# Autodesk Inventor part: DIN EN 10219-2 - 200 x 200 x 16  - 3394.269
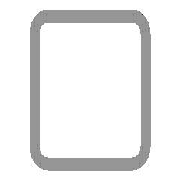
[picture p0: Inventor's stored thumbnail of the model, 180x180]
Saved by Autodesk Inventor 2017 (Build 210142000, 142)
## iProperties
IsCustomPart: 1
Created: 2016-02
Part Number: DIN EN 10219-2 - 200 x 200 x 16  - 3394.269
Material: Steel, Mild
Description: Cold formed welded structural hollow sections of non-alloy and fine grain structural steel
Document SubType Name: Modeling
Standard: DIN
Designer: iusti
Standard Revision: 2006-07
Standards Organization: DIN
Language: en-US
Size Designation: 200 x 200 x 16
Categories: <MemberInstance><Categories><Category DisplayName="Structural Shapes" InternalName="089c4875-fa83-4c05-b084-43b9cc11f5ed" Mnemonic="GRDR"><CategoryParameter Dis
Stock Number: 200 x 200 x 16
Density: 7.85 g/cm^3
Appearance: Semi-Polished
Mass: 259456 g
Surface Area: 41726.7 cm^2
Volume: 33051.7 cm^3
_CCFamilyMember: 103
_CCFamilyDisplayName: DIN EN 10219-2 (Square Hollow Section - Cold Formed) - Cold formed welded structural hollow sections of non-alloy and fine grain structural steel
_FrameMemberDoc: Frame Member File
_Version: 15.0.0
_GetPNFromCC: 1
G_L: 3394.269 mm
G_W: 200.000 mm
G_H: 200.000 mm
+04F2D6EA-35C4-4CFB-B988-CDC8EB8D103C+CUTDETAIL1: Cut
+DAF749EB-893C-4754-AD4A-1A621FA4CB9E+CUTDETAIL2: Cut
Author: iusti
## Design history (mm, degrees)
node "Start plane"
node "End plane"
sketch "Sketch"
  geometry: L1 (-100, -52)-(-100, 52); L2 (-52, 100)-(52, 100); L3 (100, 52)-(100, -52); L4 (52, -100)-(-52, -100); L5 (-52, 84)-(52, 84); L6 (84, 52)-(84, -52); L7 (52, -84)-(-52, -84); L8 (-84, -52)-(-84, 52); L9 (0, 153.918)-(0, -153.918) reference; L10 (-153.918, 0)-(153.918, 0) reference; A1 r 48 centre (-52, -52) between (-100, -52) and (-52, -100); A2 r 48 centre (-52, 52) between (-52, 100) and (-100, 52); A3 r 48 centre (52, 52) between (100, 52) and (52, 100); A4 r 48 centre (52, -52) between (52, -100) and (100, -52); A5 r 32 centre (-52, 52) between (-52, 84) and (-84, 52); A6 r 32 centre (52, 52) between (84, 52) and (52, 84); A7 r 32 centre (52, -52) between (52, -84) and (84, -52); A8 r 32 centre (-52, -52) between (-84, -52) and (-52, -84)
  constraints: 16 end point, 16 point on circle, 8 centre point, 8 tangent, 4 parallel, 3 equal radius, 2 perpendicular, 7 other
  dimensions: "d7" = 48 radius of A1 (= G_IR); "d10" = 200 distance between parallel lines of L2 L4 (= G_H); "d11" = 200 distance between parallel lines of L1 L3 (= G_W); "d12" = 16 distance between parallel lines of L3 L6 (= G_T); "d15" = 100 distance between parallel lines of L2 L10 (= 0.5 x d10); "d16" = 100 distance between parallel lines of L9 L3 (= 0.5 x d11)
extrude "Body" new body sketch "Sketch" stored distance "d3" = 3394.26947 (= G_L); taper "d4" = 0 deg
node "Driven Length"
  sketch "Sketch3"
    geometry: L1 (0, 0)-(10, 0) reference
    constraints: 2 end point, 1 horizontal
  workplane "Work Plane3"
  sketch "Sketch4"
    geometry: L1 (-2, 73.146)-(12, 73.146) reference; L2 (-2, 3467.416)-(12, 3467.416) reference
    dimensions: "d18" = 3394.26947 distance between parallel lines of L1 L2 (derived)
workplane "Work Plane4"
split "Split1"
workplane "Work Plane5"
split "Split2"
body "Solid1"
other parameters: "G_W" = 200 [user parameter; used in 1 equation term], "G_H" = 200 [user parameter; used in 1 equation term], "G_T" = 16 [user parameter; used in 1 equation term], "G_IR" = 48 [user parameter; used in 1 equation term], "G_L" = 3394.26947 (= d18) [user parameter; used in 1 equation term], "G_OFFSET_START" = -73.14647 [user parameter; used in 1 equation term], "G_OFFSET_END" = -18.54571 [user parameter; used in 1 equation term], "d13" = 73.14647 (= -G_OFFSET_START), "d14" = 3467.41594 (= G_OFFSET_END + B_L), "B_L" = 3485.96166 [user parameter; used in 1 equation term], "d17" = 90 deg
